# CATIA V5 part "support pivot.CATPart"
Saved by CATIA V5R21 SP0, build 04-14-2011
Part number: SupportPivot
Bounding box of the stored display mesh (mm): x -21 to 21, y -21 to 38, z 0 to 27
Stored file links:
  C:\Users\2027.DESARCY-LEMIE30\Desktop\Assemblage26.05\support pivot.CATPart
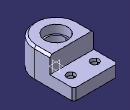
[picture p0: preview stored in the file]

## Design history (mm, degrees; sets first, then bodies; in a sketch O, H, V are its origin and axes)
Body1 (main body)
  Sketch1 on xy-plane, origin (0, 0, 0), H (1, 0, 0), V (0, 1, 0)
    arc A1 centre (0, 0) radius 21 from (-21, 0) to (21, 0) ccw
    line L1 (-21, 15) -> (21, 15)
    line L2 (21, 15) -> (21, 0)
    line L3 (-21, 0) -> (-21, 15)
    radius A1 = 21
    length L1 = 42
    distance L1 H = 15
    horizontal: L1 H
    vertical: L2 V, L3 V
  Pad1: profile Sketch1, direction (0, 0, 1), length 27
  Sketch2 on xy-plane, origin (0, 0, 0), H (1, 0, 0), V (0, 1, 0)
    line L1 (21, 0) -> (21, 38)
    line L2 (21, 38) -> (-21, 38)
    line L3 (-21, 38) -> (-21, 0)
    line L4 (-21, 0) -> (21, 0)
    distance L2 H = 38
    distance L1 V = 21
    length L2 = 42
    horizontal: L2 H, L4 H
    vertical: L1 V, L3 V
  Pad2: profile Sketch2, direction (0, 0, 1), length 11
  Sketch3 on end face of Pad1, origin (1.3571, -8.2844, 27), H (1, 0, 0), V (0, 1, 0)
    point P1 (-1.3571, 8.2844)
    reference projected arc E1 centre (-1.3571, 8.2844) radius 21 from (-22.3571, 8.2844) to (19.6429, 8.2844) ccw from edge [face of Pad1 from Sketch1.A1 | end face of Pad1]
    reference intersected line E2 through (-1.3571, 0) direction (0, 1) from yz-plane
    reference intersected line E3 through (0, 8.2844) direction (-1, 0) from zx-plane
    radius E1 = 21 (reference)
    distance P1 E2 = 0
    distance E3 P1 = 0
  Hole1: placed by Sketch3, at (0, 0, 27) direction (0, 0, -1), diameter 22, through (limit type 6)
  Sketch4 on face of Pad2, origin (-11.5216, 25.6596, 0), H (1, 0, 0), V (0, -1, 0)
    point P1 (0.0216, 0.1596)
    reference projected line E1 (-9.4784, 10.6596) -> (-9.4784, 25.6596) from edge [face of Pad2 | face of Pad2]
    reference projected line E2 (32.5216, -12.3404) -> (-9.4784, -12.3404) from edge [start face of Pad2 | face of Pad2 from Sketch2.L2]
    distance P1 E1 = 9.5
    distance P1 E2 = 12.5
  Hole2: placed by Sketch4, at (-11.5, 25.5, 0) direction (0, 0, 1), diameter 7.9, through (limit type 6), counterbore diameter 12.76, counterbore depth 8
  Sketch5 on face of Pad2, origin (12.0454, 25.2497, 0), H (1, 0, 0), V (0, -1, 0)
    point P1 (-0.5454, -0.2503)
    reference projected line E1 (8.9546, 25.2497) -> (8.9546, 10.2497) from edge [face of Pad2 | face of Pad2]
    reference projected line E2 (8.9546, -12.7503) -> (-33.0454, -12.7503) from edge [start face of Pad2 | face of Pad2 from Sketch2.L2]
    distance P1 E1 = 9.5
    distance P1 E2 = 12.5
  Hole3: placed by Sketch5, at (11.5, 25.5, 0) direction (0, 0, 1), diameter 7.9, through (limit type 6), counterbore diameter 12.76, counterbore depth 8
  Chamfer1: length 2, angle 45, on edge [face of Pad2 from Sketch2.L2 | face of Pad2]
  Chamfer2: length 2, angle 45, on edge [face of Pad1 from Sketch1.A1 | end face of Pad1]
  Chamfer3: length 2, angle 45, on edge [face of Pad2 | face of Pad2 from Sketch2.L2]
  Sketch6 on xy-plane, origin (0, 0, 0), H (1, 0, 0), V (0, 1, 0)
    circle A1 centre (0, 0) radius 9.5
    projected circle E1 centre (0, 0) radius 11 from edge [end face of Pad1 | face of Hole1]
    radius A1 = 9.5
  Pad3: profile Sketch6, direction (0, 0, 1), length 19, opposite side length -7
